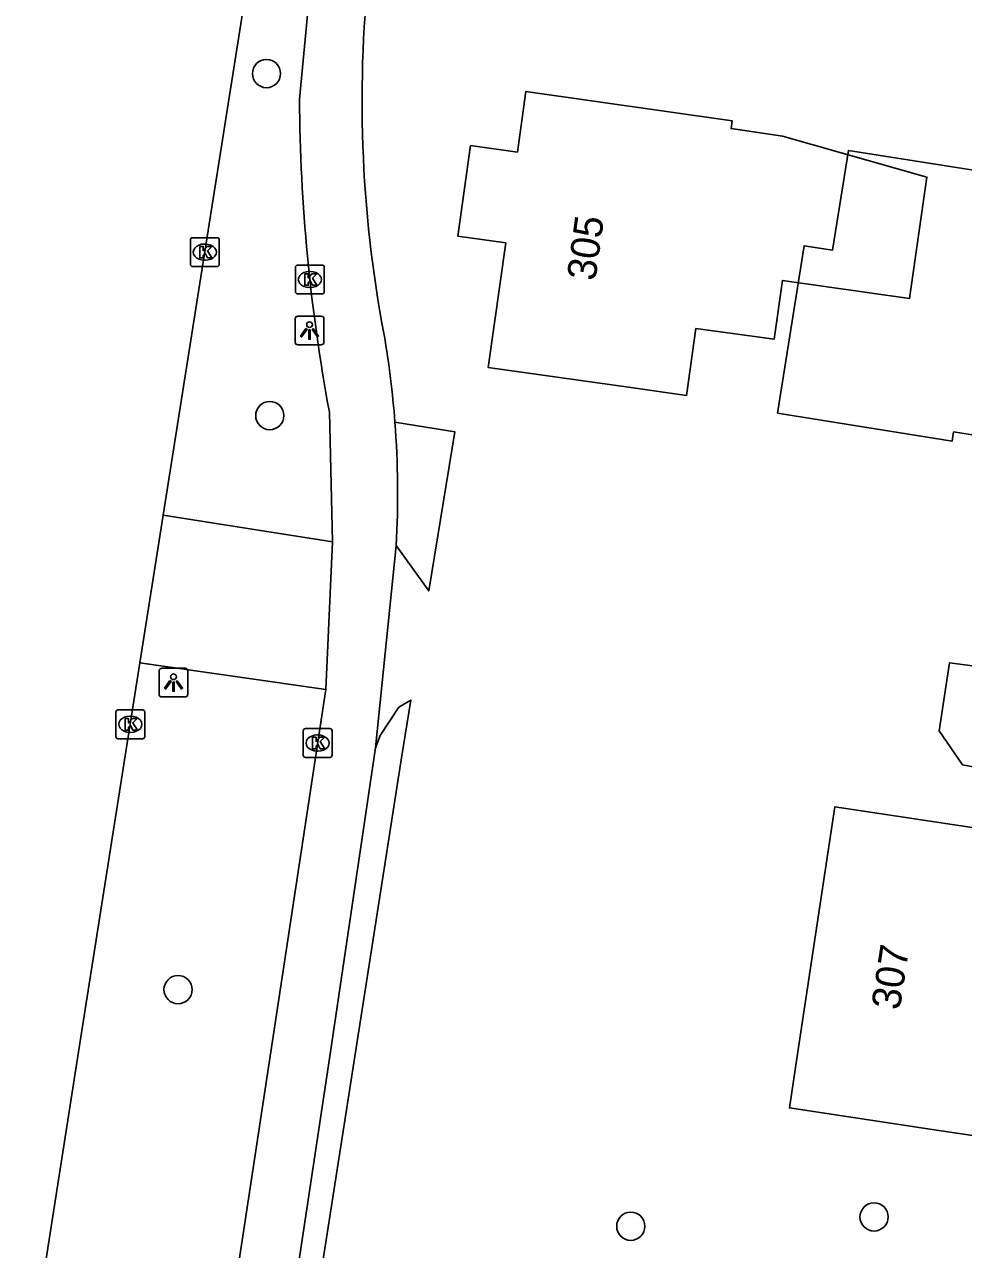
# Model space of a CAD drawing. Extents: x 161486 to 162249, y 379484 to 380829.
# Drawn here: x 161608.16 to 161640.71, y 380243.15 to 380285.63 of the extents above; entities that cross this region are included whole.
import ezdxf

# ---------------------------------------------------------------- set-up
doc = ezdxf.new("R2010")
doc.units = 0
for name, color, linetype in [('IMGEO_Boom', 7, 'Continuous'), ('IMGEO_Fietspad_open', 7, 'Continuous'), ('IMGEO_Grasland_overig', 7, 'Continuous'), ('IMGEO_Groenvoorziening', 7, 'Continuous'), ('IMGEO_Kolk', 7, 'Continuous'), ('IMGEO_Lichtpunt', 7, 'Continuous'), ('IMGEO_Pand', 7, 'Continuous'), ('IMGEO_Pand_nummerreeks', 7, 'Continuous'), ('IMGEO_Pand_vergunning_verleend', 7, 'Continuous'), ('IMGEO_Rijbaan_lokaal_open', 7, 'Continuous'), ('IMGEO_Rijbaan_regionaal_gesloten', 7, 'Continuous')]:
    doc.layers.add(name, color=color, linetype=linetype)

msp = doc.modelspace()

# ---------------------------------------------------------------- linework, layer by layer
at = {"layer": 'IMGEO_Boom'}
for centre in [(161616.545, 380283.926), (161616.659, 380272.066), (161613.48, 380252.161), (161637.608, 380244.279), (161629.174, 380243.956)]:
    msp.add_circle(centre, 0.489, dxfattribs=at)
at = {"layer": 'IMGEO_Fietspad_open'}
for points in [[(161617.689, 380283.035), (161618.188, 380288.29), (161618.631, 380292.951), (161619.891, 380303.019)], [(161618.836, 380267.694), (161618.727, 380272.19)], [(161621.037, 380267.559), (161620.322, 380260.549)], [(161614.985, 380238.749), (161616.692, 380250), (161618.598, 380262.565)], [(161620.322, 380260.549), (161618.769, 380250), (161609.481, 380188.437)]]:
    msp.add_lwpolyline(points, dxfattribs=at)
for centre, radius, start, end in [((161663.267, 380282.973), 43.409, 173.3311, 190.7634), ((161678.582, 380283.391), 60.894, 180.33498, 190.59953), ((161588.985, 380269.42), 32.103, 4.3239, 9.7677), ((161588.89, 380269.392), 32.2, 356.7369, 4.3605)]:
    msp.add_arc(centre, radius, start, end, dxfattribs=at)
at = {"layer": 'IMGEO_Grasland_overig'}
msp.add_lwpolyline([(161620.996, 380271.84), (161623.073, 380271.504), (161622.17, 380265.99), (161621.037, 380267.559)], dxfattribs=at)
at = {"layer": 'IMGEO_Groenvoorziening'}
msp.add_lwpolyline([(161620.322, 380260.549), (161620.489, 380260.968), (161621.137, 380261.951), (161621.549, 380262.195), (161621.222, 380260.199), (161618.504, 380242.815), (161613.182, 380208.331), (161610.196, 380188.326), (161609.481, 380188.437)], dxfattribs=at)
at = {"layer": 'IMGEO_Kolk'}
for p, q in [((161613.907, 380277.309), (161613.907, 380278.161)), ((161613.982, 380278.235), (161614.834, 380278.235)), ((161614.908, 380278.161), (161614.908, 380277.309)), ((161614.395, 380278.015), (161614.42, 380278.015)), ((161614.418, 380277.455), (161614.393, 380277.455)), ((161617.623, 380277.286), (161618.475, 380277.286)), ((161614.834, 380277.235), (161613.982, 380277.235)), ((161617.548, 380276.36), (161617.548, 380277.212)), ((161618.036, 380277.066), (161618.061, 380277.066)), ((161618.549, 380277.212), (161618.549, 380276.36)), ((161618.059, 380276.506), (161618.034, 380276.506)), ((161618.475, 380276.286), (161617.623, 380276.286)), ((161611.322, 380260.937), (161611.322, 380261.789)), ((161611.397, 380261.863), (161612.249, 380261.863)), ((161611.81, 380261.643), (161611.835, 380261.643)), ((161612.323, 380261.789), (161612.323, 380260.937)), ((161617.817, 380260.287), (161617.817, 380261.139)), ((161617.892, 380261.213), (161618.744, 380261.213)), ((161618.818, 380261.139), (161618.818, 380260.287)), ((161612.249, 380260.863), (161611.397, 380260.863)), ((161611.833, 380261.083), (161611.808, 380261.083)), ((161618.305, 380260.993), (161618.33, 380260.993)), ((161618.328, 380260.433), (161618.303, 380260.433)), ((161618.744, 380260.213), (161617.892, 380260.213))]:
    msp.add_line(p, q, dxfattribs=at)
for points in [[(161613.907, 380277.309), (161613.907, 380278.161)], [(161613.982, 380278.235), (161614.834, 380278.235)], [(161614.908, 380278.161), (161614.908, 380277.309)], [(161614.228, 380277.935), (161614.351, 380277.935), (161614.351, 380277.784), (161614.481, 380277.935), (161614.645, 380277.935), (161614.499, 380277.784), (161614.652, 380277.535), (161614.5, 380277.535), (161614.415, 380277.699), (161614.351, 380277.632), (161614.351, 380277.535), (161614.228, 380277.535), (161614.228, 380277.935)], [(161617.623, 380277.286), (161618.475, 380277.286)], [(161614.834, 380277.235), (161613.982, 380277.235)], [(161617.548, 380276.36), (161617.548, 380277.212)], [(161617.869, 380276.986), (161617.992, 380276.986), (161617.992, 380276.835), (161618.122, 380276.986), (161618.286, 380276.986), (161618.14, 380276.835), (161618.293, 380276.586), (161618.141, 380276.586), (161618.056, 380276.75), (161617.992, 380276.683), (161617.992, 380276.586), (161617.869, 380276.586), (161617.869, 380276.986)], [(161618.549, 380277.212), (161618.549, 380276.36)], [(161618.475, 380276.286), (161617.623, 380276.286)], [(161611.322, 380260.937), (161611.322, 380261.789)], [(161611.397, 380261.863), (161612.249, 380261.863)], [(161611.643, 380261.563), (161611.766, 380261.563), (161611.766, 380261.412), (161611.896, 380261.563), (161612.06, 380261.563), (161611.914, 380261.412), (161612.067, 380261.163), (161611.915, 380261.163), (161611.83, 380261.327), (161611.766, 380261.26), (161611.766, 380261.163), (161611.643, 380261.163), (161611.643, 380261.563)], [(161612.323, 380261.789), (161612.323, 380260.937)], [(161617.817, 380260.287), (161617.817, 380261.139)], [(161617.892, 380261.213), (161618.744, 380261.213)], [(161618.818, 380261.139), (161618.818, 380260.287)], [(161612.249, 380260.863), (161611.397, 380260.863)], [(161618.138, 380260.913), (161618.261, 380260.913), (161618.261, 380260.762), (161618.391, 380260.913), (161618.555, 380260.913), (161618.409, 380260.762), (161618.562, 380260.513), (161618.41, 380260.513), (161618.325, 380260.677), (161618.261, 380260.61), (161618.261, 380260.513), (161618.138, 380260.513), (161618.138, 380260.913)], [(161618.744, 380260.213), (161617.892, 380260.213)]]:
    msp.add_lwpolyline(points, dxfattribs=at)
for centre, start, end in [((161613.984, 380278.159), 91.552, 178.448), ((161613.984, 380278.159), 91.552, 178.448), ((161614.832, 380278.159), 1.552, 88.448), ((161614.832, 380278.159), 1.552, 88.448), ((161613.984, 380277.311), 181.552, 268.448), ((161613.984, 380277.311), 181.552, 268.448), ((161614.832, 380277.311), 271.552, 358.448), ((161614.832, 380277.311), 271.552, 358.448), ((161617.625, 380277.21), 91.552, 178.448), ((161617.625, 380277.21), 91.552, 178.448), ((161618.473, 380277.21), 1.552, 88.448), ((161618.473, 380277.21), 1.552, 88.448), ((161617.625, 380276.362), 181.552, 268.448), ((161617.625, 380276.362), 181.552, 268.448), ((161618.473, 380276.362), 271.552, 358.448), ((161618.473, 380276.362), 271.552, 358.448), ((161611.399, 380261.787), 91.552, 178.448), ((161611.399, 380261.787), 91.552, 178.448), ((161612.247, 380261.787), 1.552, 88.448), ((161612.247, 380261.787), 1.552, 88.448), ((161617.894, 380261.137), 91.552, 178.448), ((161617.894, 380261.137), 91.552, 178.448), ((161618.742, 380261.137), 1.552, 88.448), ((161618.742, 380261.137), 1.552, 88.448), ((161611.399, 380260.939), 181.552, 268.448), ((161611.399, 380260.939), 181.552, 268.448), ((161612.247, 380260.939), 271.552, 358.448), ((161612.247, 380260.939), 271.552, 358.448), ((161617.894, 380260.289), 181.552, 268.448), ((161617.894, 380260.289), 181.552, 268.448), ((161618.742, 380260.289), 271.552, 358.448), ((161618.742, 380260.289), 271.552, 358.448)]:
    msp.add_arc(centre, 0.0765, start, end, dxfattribs=at)
for centre, major_axis, ratio, start_param, end_param in [((161614.394, 380277.735), (-0.387, 0.002), 0.722429, 4.712389, 7.853982), ((161614.419, 380277.735), (-0.39, 0.002), 0.717154, 1.570796, 4.712389), ((161618.035, 380276.786), (-0.387, 0.002), 0.722429, 4.712389, 7.853982), ((161618.06, 380276.786), (-0.39, 0.002), 0.717154, 1.570796, 4.712389), ((161611.809, 380261.363), (-0.387, 0.002), 0.722429, 4.712389, 7.853982), ((161611.834, 380261.363), (-0.39, 0.002), 0.717154, 1.570796, 4.712389), ((161618.304, 380260.713), (-0.387, 0.002), 0.722429, 4.712389, 7.853982), ((161618.329, 380260.713), (-0.39, 0.002), 0.717154, 1.570796, 4.712389)]:
    msp.add_ellipse(centre, major_axis=major_axis, ratio=ratio, start_param=start_param, end_param=end_param, dxfattribs=at)
at = {"layer": 'IMGEO_Lichtpunt'}
for p, q in [((161617.538, 380275.421), (161617.538, 380274.614)), ((161617.538, 380275.421), (161617.538, 380274.614)), ((161618.44, 380275.516), (161617.632, 380275.516)), ((161618.44, 380275.516), (161617.632, 380275.516)), ((161618.534, 380274.614), (161618.534, 380275.421)), ((161618.534, 380274.614), (161618.534, 380275.421)), ((161617.632, 380274.52), (161618.44, 380274.52)), ((161617.632, 380274.52), (161618.44, 380274.52)), ((161613.724, 380263.307), (161612.916, 380263.307)), ((161613.724, 380263.307), (161612.916, 380263.307)), ((161612.822, 380263.212), (161612.822, 380262.405)), ((161612.822, 380263.212), (161612.822, 380262.405)), ((161613.818, 380262.405), (161613.818, 380263.212)), ((161613.818, 380262.405), (161613.818, 380263.212)), ((161612.916, 380262.311), (161613.724, 380262.311)), ((161612.916, 380262.311), (161613.724, 380262.311))]:
    msp.add_line(p, q, dxfattribs=at)
for points in [[(161617.912, 380275.085), (161617.951, 380275.057), (161617.763, 380274.795), (161617.725, 380274.822), (161617.912, 380275.085)], [(161618.014, 380275.037), (161618.061, 380275.037), (161618.061, 380274.715), (161618.014, 380274.715), (161618.014, 380275.037)], [(161618.124, 380275.057), (161618.162, 380275.084), (161618.349, 380274.822), (161618.31, 380274.794), (161618.124, 380275.057)], [(161613.196, 380262.876), (161613.235, 380262.848), (161613.047, 380262.586), (161613.009, 380262.613), (161613.196, 380262.876)], [(161613.408, 380262.848), (161613.446, 380262.875), (161613.633, 380262.613), (161613.594, 380262.585), (161613.408, 380262.848)], [(161613.298, 380262.828), (161613.345, 380262.828), (161613.345, 380262.506), (161613.298, 380262.506), (161613.298, 380262.828)]]:
    msp.add_lwpolyline(points, dxfattribs=at)
for centre in [(161618.037, 380275.219), (161613.321, 380263.01)]:
    msp.add_circle(centre, 0.0994, dxfattribs=at)
for centre, start, end in [((161617.632, 380275.421), 90, 180), ((161617.632, 380275.421), 90, 180), ((161618.44, 380275.421), 0, 90), ((161618.44, 380275.421), 0, 90), ((161617.632, 380274.614), 180, 270), ((161617.632, 380274.614), 180, 270), ((161618.44, 380274.614), 270, 0), ((161618.44, 380274.614), 270, 360), ((161612.916, 380263.212), 90, 180), ((161612.916, 380263.212), 90, 180), ((161613.724, 380263.212), 0, 90), ((161613.724, 380263.212), 0, 90), ((161612.916, 380262.405), 180, 270), ((161612.916, 380262.405), 180, 270), ((161613.724, 380262.405), 270, 0), ((161613.724, 380262.405), 270, 360)]:
    msp.add_arc(centre, 0.0946, start, end, dxfattribs=at)
at = {"layer": 'IMGEO_Pand'}
for points in [[(161631.11, 380272.761), (161629.178, 380273.036), (161624.227, 380273.739), (161624.84, 380278.054), (161623.174, 380278.291), (161623.62, 380281.431), (161625.241, 380281.201), (161625.54, 380283.307), (161632.688, 380282.291), (161632.649, 380282.019), (161634.437, 380281.761), (161639.438, 380280.336), (161638.84, 380276.129), (161634.429, 380276.756), (161634.139, 380274.713), (161631.433, 380275.087), (161631.11, 380272.761)], [(161648.333, 380246.005), (161644.36, 380246.602), (161639.619, 380247.315), (161634.674, 380248.059), (161634.966, 380250), (161636.244, 380258.495), (161638.395, 380258.171), (161641.62, 380257.686), (161641.926, 380259.721), (161640.668, 380259.958), (161639.865, 380261.136), (161640.223, 380263.496), (161641.288, 380263.355), (161641.363, 380263.779), (161646.438, 380263.035), (161650.797, 380262.379), (161649.903, 380256.439), (161649.22, 380251.899), (161648.333, 380246.005)]]:
    msp.add_lwpolyline(points, dxfattribs=at)
at = {"layer": 'IMGEO_Pand_vergunning_verleend'}
msp.add_lwpolyline([(161634.258, 380272.145), (161635.183, 380277.958), (161636.166, 380277.801), (161636.716, 380281.264), (161641.498, 380280.503), (161641.519, 380280.641), (161643.05, 380280.397), (161643.558, 380283.589), (161649.461, 380282.651), (161648.934, 380279.334), (161649.931, 380279.176), (161648.993, 380273.275), (161648.36, 380273.376), (161647.872, 380270.305), (161640.367, 380271.498), (161640.317, 380271.182), (161634.258, 380272.145)], dxfattribs=at)
at = {"layer": 'IMGEO_Rijbaan_lokaal_open'}
for points in [[(161618.836, 380267.694), (161612.966, 380268.612)], [(161618.598, 380262.565), (161618.836, 380267.694)], [(161612.157, 380263.491), (161618.598, 380262.565)]]:
    msp.add_lwpolyline(points, dxfattribs=at)
at = {"layer": 'IMGEO_Rijbaan_regionaal_gesloten'}
for points in [[(161561.452, 379936.044), (161563.672, 379950.77), (161563.73, 379951.16), (161563.762, 379951.37), (161564.733, 379957.682), (161571.244, 380000), (161582.203, 380071.227), (161587.4, 380105.007), (161597.03, 380166.719), (161597.942, 380172.561), (161599.892, 380185.059), (161600.825, 380191.04), (161602.895, 380204.301), (161603.827, 380210.276), (161607.628, 380234.634), (161608.561, 380240.609), (161610.026, 380250), (161612.157, 380263.491), (161612.966, 380268.612), (161616.121, 380288.581), (161617.778, 380299.073)], [(161612.966, 380268.612), (161616.121, 380288.581), (161617.778, 380299.073)], [(161612.157, 380263.491), (161612.966, 380268.612)], [(161608.561, 380240.609), (161610.026, 380250), (161612.157, 380263.491)]]:
    msp.add_lwpolyline(points, dxfattribs=at)

# ---------------------------------------------------------------- texts
at = {"layer": 'IMGEO_Pand_nummerreeks'}
for s, rotation, p in [('305', 82.1862, (161627.946, 380276.712)), ('307', 81.446, (161638.498, 380251.427))]:
    msp.add_text(s, height=1, rotation=rotation, dxfattribs=at).set_placement(p)

doc.saveas('drawing.dxf')
